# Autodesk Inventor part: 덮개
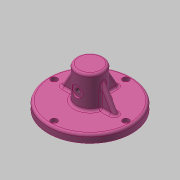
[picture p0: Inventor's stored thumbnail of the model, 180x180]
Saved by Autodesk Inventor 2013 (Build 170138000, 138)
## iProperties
Created: 2017-08
Part Number: 덮개
Material: 알루미늄 6061
Document SubType Name: Modeling
Designer: mduedu
Density: 2.71 g/cm^3
Mass: 336.254 g
Surface Area: 314.322 cm^2
Volume: 124.079 cm^3
Author: mduedu
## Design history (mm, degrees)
sketch "스케치1"
  geometry: C1 r 52.5 at (0, 0); 1 further point
  constraints: 1 centre point, 1 coincident
  dimensions: "d55" = 105 diameter of C1
extrude "돌출1" new body sketch "스케치1" distance "d5" = 10; taper "d6" = 0 deg
sketch "스케치2"
  geometry: C1 r 17 at (0, 0); 1 further point
  constraints: 1 centre point, 1 coincident
  dimensions: "d74" = 34 diameter of C1
extrude "돌출2" join sketch "스케치2" distance "d9" = 40; taper "d10" = 0 deg
sketch "스케치3"
  geometry: C1 r 37 at (0, 0); 1 further point
  constraints: 1 centre point, 1 coincident
  dimensions: "d56" = 74 diameter of C1
extrude "돌출3" join sketch "스케치3" distance "d12" = 8; taper "d13" = 0 deg
sketch "스케치4"
  geometry: C1 r 33 at (0, 0); 1 further point
  constraints: 1 centre point, 1 coincident
  dimensions: "d57" = 66 diameter of C1
extrude "돌출4" cut sketch "스케치4" distance "d16" = 7; taper "d17" = 0 deg
sketch "스케치5"
  geometry: C1 r 9 at (0, 0); 1 further point
  constraints: 1 centre point, 1 coincident
  dimensions: "d18" = 18 diameter of C1
extrude "돌출5" cut sketch "스케치5" distance "d19" = 47; taper "d20" = 0 deg
node "작업 평면1"
sketch "스케치11"
  geometry: L1 (-52.5, -10)-(52.5, -10) reference; 2 further points
  constraints: 1 vertical alignment
  dimensions: "d78" = 28 distance from line of point (0, 18) L1
hole "구멍5" sketch "스케치11" at (0, 18) diameter "d79" = 5.917; stored, may be unused: countersink angle "d83" = 90 deg, drill point angle "d85" = 118 deg; dims "d80" = 6, "d81" = 14, "d82" = 2, "d84" = 8
fillet "모깎기9" dims "d86" = 3
fillet "모깎기5" dims "d40" = 1
sketch "스케치12"
  geometry: C1 r 2.5 at (0, 0); 1 further point
  constraints: 1 centre point, 1 coincident
  dimensions: "d87" = 5 diameter of C1
extrude "돌출6" join sketch "스케치12" distance "d88" = 3; taper "d89" = 0 deg
fillet "모깎기10" dims "d91" = 1
chamfer "모따기1" distance "d41" = 1; stored, may be unused: second distance "d42" = 2, angle "d43" = 45 deg
fillet "모깎기7" dims "d45" = 3
fillet "모깎기8" dims "d46" = 3
sketch "스케치10" dims "d59" = 90
  geometry: 3 further points
  constraints: 2 vertical alignment, 1 coincident, 2 other
hole "구멍4" sketch "스케치10" at (0, 45) diameter "d60" = 4.5; stored, may be unused: countersink angle "d64" = 90 deg, drill point angle "d66" = 118 deg; dims "d61" = 6, "d62" = 8, "d63" = 4.6, "d65" = 8
sketch "스케치13"
  geometry: L1 (52.5, 7)-(52.5, 0) reference; L2 (52.5, 0)-(47.25, 0) reference; L3 (47.25, 0)-(47.25, 5.4) reference; L4 (47.25, 5.4)-(49, 5.4) reference; L5 (49, 5.4)-(49, 10) reference; L6 (49, 10)-(49.5, 10) reference; L7 (-49.5, 10)-(-49, 10) reference; L8 (-49, 10)-(-49, 5.4) reference; L9 (-49, 5.4)-(-47.25, 5.4) reference; L10 (-47.25, 5.4)-(-47.25, 0) reference; L11 (-47.25, 0)-(-52.5, 0) reference; L12 (-52.5, 0)-(-52.5, 7) reference; L13 (-3.5, 46)-(-8, 46) reference; L14 (-9, 45)-(-9, -1) reference; L15 (-9, -1)-(-30, -1) reference; L16 (-33, -4)-(-33, -8) reference; L17 (-33, -8)-(-36, -8) reference; L18 (-36, -8)-(-37, -7) reference; L19 (-37, -7)-(-37, 0) reference; L20 (-37, 0)-(-42.75, 0) reference; L21 (-42.75, 0)-(-42.75, 5.4) reference; L22 (-42.75, 5.4)-(-41, 5.4) reference; L23 (-41, 5.4)-(-41, 10) reference; L24 (-41, 10)-(-20, 10) reference; L25 (-17, 13)-(-17, 47) reference; L26 (-14, 50)-(14, 50) reference; L27 (17, 47)-(17, 13) reference; L28 (20, 10)-(41, 10) reference; L29 (41, 10)-(41, 5.4) reference; L30 (41, 5.4)-(42.75, 5.4) reference; L31 (42.75, 5.4)-(42.75, 0) reference; L32 (42.75, 0)-(37, 0) reference; L33 (37, 0)-(37, -7) reference; L34 (37, -7)-(36, -8) reference; L35 (36, -8)-(33, -8) reference; L36 (33, -8)-(33, -4) reference; L37 (30, -1)-(9, -1) reference; L38 (9, -1)-(9, 45) reference; L39 (8, 46)-(3.5, 46) reference; L40 (2.5, 45)-(2.5, 43) reference; L41 (2.5, 43)-(-2.5, 43) reference; L42 (-2.5, 43)-(-2.5, 45) reference; L43 (17, 40)-(34.321, 10); L44 (-49.5, 10)-(49.5, 10) reference; A1 r 3 centre (49.5, 7) between (52.5, 7) and (49.5, 10) reference; A2 r 3 centre (-49.5, 7) between (-49.5, 10) and (-52.5, 7) reference; A3 r 1 centre (-3.5, 45) between (-2.5, 45) and (-3.5, 46) reference; A4 r 1 centre (-8, 45) between (-8, 46) and (-9, 45) reference; A5 r 3 centre (-30, -4) between (-30, -1) and (-33, -4) reference; A6 r 3 centre (-20, 13) between (-20, 10) and (-17, 13) reference; A7 r 3 centre (-14, 47) between (-14, 50) and (-17, 47) reference; A8 r 3 centre (14, 47) between (17, 47) and (14, 50) reference; A9 r 3 centre (20, 13) between (17, 13) and (20, 10) reference; A10 r 3 centre (30, -4) between (33, -4) and (30, -1) reference; A11 r 1 centre (8, 45) between (9, 45) and (8, 46) reference; A12 r 1 centre (3.5, 45) between (3.5, 46) and (2.5, 45) reference; 1 further point
  constraints: 2 end point, 2 point on line
  dimensions: "d98" = 120 deg angle of L43 L28; "d99" = 30 distance from line of L43.start L44
feature "리브1" sketch "스케치13" dims "d100" = 1, "d101" = 6, "d102" = 0, "d103" = 0, "d104" = 1, "d105" = 1
fillet "모깎기11" dims "d106" = 3
fillet "모깎기12" dims "d107" = 3
node "솔리드1"
pattern_circular "원형 패턴1" dims angle "d68" = 360 deg
pattern_circular "원형 패턴2" dims "d109" = 270 deg
node "절단 모서리 투영1"
